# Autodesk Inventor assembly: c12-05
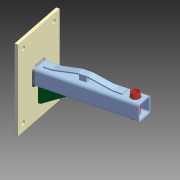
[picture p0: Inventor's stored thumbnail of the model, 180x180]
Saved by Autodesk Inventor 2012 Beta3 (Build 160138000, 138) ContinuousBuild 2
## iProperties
Created: 2011-01
Part Number: c12-05
Document SubType Name: Weldment
Designer: Beta-8540w
Weld Material: Welded Steel Mild
_SolveAssemblyDoc: Frame Generator Solve Assembly
_Version: 15.0.0
Author: Beta-8540w
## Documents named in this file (5)
- C:\Inventor 2012 Essentials\Assemblies\Chapter 12\c12-05.iam
- C:\Inventor 2012 Essentials\Parts\Chapter 12\c12-01.ipt
- C:\Inventor 2012 Essentials\Parts\Chapter 12\c12-02.ipt
- C:\Inventor 2012 Essentials\Assemblies\Chapter 12\Frame\Frame c12-01.iam
- C:\Inventor 2012 Essentials\Parts\Chapter 12\c12-03.ipt
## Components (4 placed, 4 different names)
1. c12-01:1 — Mate:2
2. c12-02:1 — Flush:1
3. Frame c12-01:1 [sub-assembly] — Mate:3
4. c12-03:1 — Mate:1, Mate:2, Mate:3
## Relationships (4: Mate 3, Flush 1)
- Flush:1: c12-02:1
- Mate:1: c12-03:1
- Mate:2: c12-01:1 ↔ c12-03:1
- Mate:3: Frame c12-01:1 ↔ c12-03:1
